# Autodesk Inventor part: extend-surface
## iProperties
Shininess: 64.0
Length Units: 11269
Angle Units: 11279
Time Units: 11290
Mass Units: 11283
Length Display Precision: 3
Angle Display Precision: 2
Compacted: True
Part Number: extend-surface
Document SubType Name: Modeling
Created: 2003-08
Designer: Owner
Manufacturer: Standard
Standards Organization: Custom
Density: 1 g/cm^3
Density: 0.0
Volumn: 0.0
Area: 0.0
PropertySet Name: Model Information
Control State: 0
Master: False
Checked Out: False
Author: Owner
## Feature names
1. Split6
